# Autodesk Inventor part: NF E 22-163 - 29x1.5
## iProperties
Component Type: 1
Library Location: C:\Program Files\Autodesk\Inventor 6\content
Library: local
SubLibrary: AFNOR
Family: 169
Member: 340
Member Major Revision: 1
Member Minor Revision: 1
Comments: To add or edit properties for Autodesk Inventor files, use iProperties.
Created: 2004-09
Part Number: NF E 22-163 - 29x1.5
Vendor: Autodesk Inc.
Document SubType Name: Modeling
Designer: Laurent
Description: Rondelle élastique d'arrêt
Standard: NF E 22-163 29x1.5
Density: 1 g/cm^3
Alert: To add or edit properties for Autodesk Inventor files, use iProperties.
Control State: 0
Master: False
Checked Out: False
Shininess: 64.0
Length Units: 11269
Angle Units: 11279
Time Units: 11290
Mass Units: 11283
Length Display Precision: 3
Angle Display Precision: 2
Compacted: True
Density: 0.0
Volumn: 0.0
Area: 0.0
PropertySet Name: Model Information
Author: Laurent
Revision Number: 1
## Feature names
1. Corps [Extrusion]
